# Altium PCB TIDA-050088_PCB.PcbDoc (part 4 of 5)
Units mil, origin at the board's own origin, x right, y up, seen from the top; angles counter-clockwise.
Board outline 8500 x 7000 mil, 8 copper layers (Top Layer, Layer 1 - GND, Signal Layer 2, Layer 3 - GND, Layer 4 - Power, Signal Layer 5, Layer 6 - GND, Bottom Layer), stack 61.6 mil thick; 537 components, 169 nets, 1427 pads, 1411 vias.
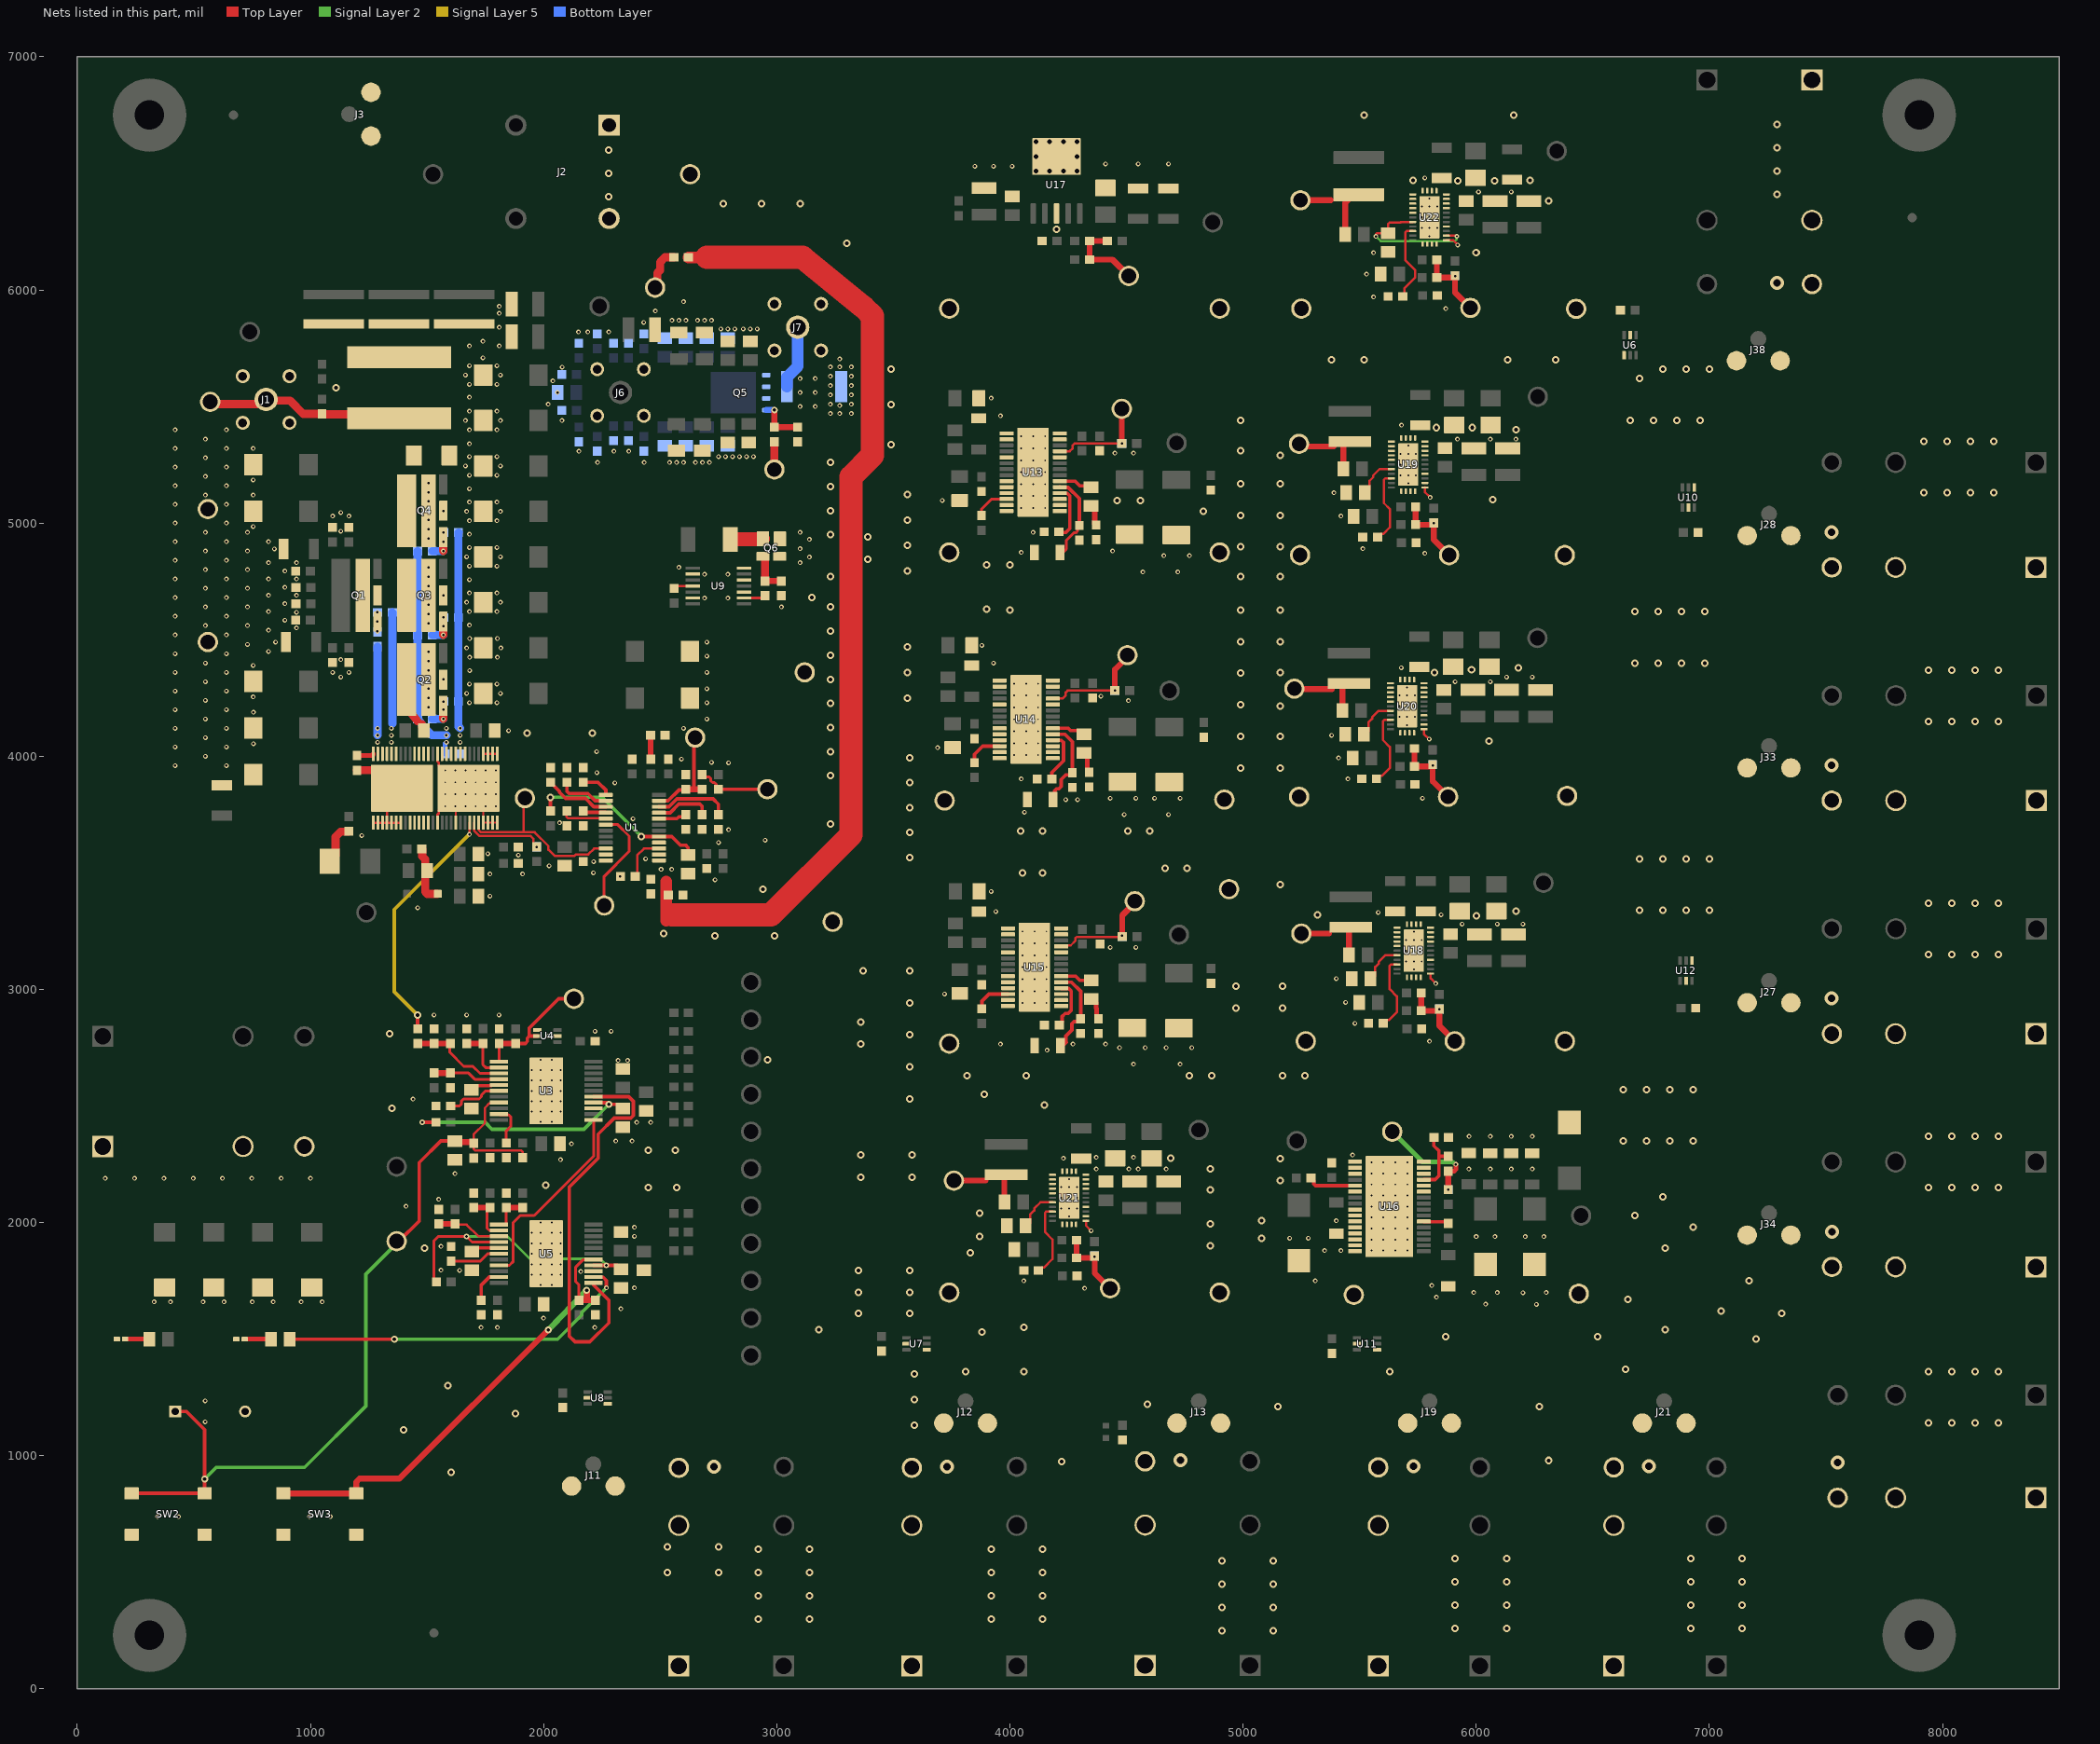
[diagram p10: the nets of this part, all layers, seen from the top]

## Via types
v1: diameter 20, hole 10, Top Layer to Bottom Layer, 671 vias
v2: diameter 32, hole 16, Top Layer to Bottom Layer, tented both sides, 369 vias
v3: diameter 19.68, hole 7.87, Top Layer to Bottom Layer, 176 vias
v4: diameter 19.68, hole 7.87, Top Layer to Bottom Layer, tented both sides, 60 vias
v5: diameter 32, hole 16, Top Layer to Bottom Layer, 30 vias
v6: diameter 56, hole 28, Top Layer to Bottom Layer, 26 vias
v7: diameter 30, hole 15, Top Layer to Bottom Layer, 24 vias
v8: diameter 60, hole 32, Top Layer to Bottom Layer, 22 vias
v9: diameter 20, hole 10, Top Layer to Bottom Layer, tented both sides, 15 vias
v10: diameter 31.5, hole 19.68, Top Layer to Bottom Layer, 10 vias
v11: diameter 24, hole 12, Top Layer to Bottom Layer, 6 vias
v12: diameter 20, hole 8, Top Layer to Bottom Layer, tented both sides, 1 vias
v13: diameter 28, hole 14, Top Layer to Bottom Layer, 1 vias

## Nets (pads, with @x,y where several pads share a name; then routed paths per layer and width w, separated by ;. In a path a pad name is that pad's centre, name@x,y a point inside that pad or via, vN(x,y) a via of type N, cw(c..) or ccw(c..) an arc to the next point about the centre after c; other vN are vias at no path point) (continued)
GND: C1.1 C2.1 C3.1 C4.1 C5.1 C6.2 C7.2 C8.2 C9.2 C10.2 C11.2 C12.2 C13.2 C14.2 C15.2 C16.2 C25.2 C26.2 C27.2 C28.2 C32.1 C33.1 C34.1 C35.1 C36.1 C37.1 C38.1 C39.1 C40.1 C41.1 C43.2 C44.1 C45.1 C46.1 C47.1 C48.2 C49.2 C50.2 C51.2 C52.2 C53.2 C54.2 C55.2 C56.2 C57.2 C58.2 C59.2 C60.2 C61.2 C62.2 C63.2 C64.2 C65.2 C66.2 C67.2 C68.2 C69.2 C70.2 C71.2 C72.2 C73.2 C74.2 C75.2 C76.2 C77.2 C78.2 C79.2 C80.2 C81.2 C82.2 C83.2 C84.2 C85.2 C86.2 C87.2 C88.2 C89.2 C90.1 C91.2 C92.2 C93.2 C94.2 C95.2 C96.2 C97.2 C98.2 C99.1 C100.1 C101.1 C102.1 C103.2 C104.2 C105.2 C106.2 C107.2 C108.2 C109.2 C110.2 C111.2 C113.2 C114.2 C115.2 C117.2 C118.1 C119.1 C120.2 C121.2 C122.2 C123.2 C124.2 C125.2 C126.2 C127.2 C128.2 C129.2 C130.2 C131.2 C132.2 C133.2 C134.2 C135.2 C136.2 C138.2 C139.2 C140.2 C141.2 C142.2 C143.2 C147.2 C148.2 C149.2 C150.2 C151.2 C152.2 C153.2 C154.2 C155.2 C156.2 C157.2 C158.2 C159.2 C160.2 C161.2 C164.2 C165.2 C168.2 C169.2 C170.2 C171.2 C172.2 C173.2 C174.2 C175.2 C176.2 C177.2 C178.2 C179.2 C180.2 C181.2 C182.2 C185.2 C186.2 C188.2 C189.2 C190.2 C191.2 C192.2 C193.2 C194.2 C196.2 D3.2 D4.2 D5.2 J1.2 J1.3 J1.4 J1.5 J2.1 J3.2 J3.3 J5.1 J5.2 J6.2 J6.3 J6.4 J6.5 J7.2 J7.3 J7.4 J7.5 J11.2 J11.3 J12.2 J12.3 J13.2 J13.3 J14.1 J14.2 J15.1 J15.2 J16.1 J16.2 J19.2 J19.3 J21.2 J21.3 J22.1 J22.2 J23.1 J23.2 J24.1 J24.2 J27.2 J27.3 J28.2 J28.3 J29.1 J29.2 J30.1 J30.2 J33.2 J33.3 J34.2 J34.3 J35.1 J35.2 J36.1 J36.2 J38.2 J38.3 J39.1 J39.2 pad.15 pad.19 pad.25 pad.26 pad.27 pad.28 pad.29 pad.30 pad.31 pad.32 pad.42 pad.58 Q2.4 Q2.5 Q3.4 Q3.5 Q4.4 Q4.5 Q6.3 Q6.4 R16.1 R17.1 R24.1 R26.1 R35.1 R37.1 R38.1 R50.1 R51.1 R52.1 R55.1 R56.1 R57.1 R58.1 R60.1 R67.1 R69.1 R70.1 R71.1 R72.1 R73.1 R75.1 R78.1 R89.1 R90.1 R91.1 R92.1 R93.1 R94.1 R95.1 R96.1 R107.1 R108.1 R109.1 R110.1 R114.1 R123.1 R124.1 R125.1 R126.1 R133.1 R134.1 R135.1 R136.1 R140.1 R141.1 SW1.2 SW2.2 SW2.4 SW3.2 SW3.4 TP10.1 TP11.1 TP12.1 TP13.1 TP14.1 TP15.1 TP17.1 TP40.1 TP41.1 TP42.1 TP43.1 TP44.1 TP45.1 TP46.1 TP55.1 TP56.1 TP57.1 TP58.1 TP59.1 TP60.1 TP61.1 TP64.1 TP65.1 TP74.1 TP75.1 TP76.1 TP77.1 TP78.1 TP79.1 TP88.1 TP89.1 TP90.1 TP91.1 TP92.1 TP93.1 TP98.1 TP99.1 TP100.1 U3.14 U3.23 U4.2 U4.4 U5.14 U5.23 U6.2 U6.4 U7.2 U7.4 U8.2 U8.4 U9.3 U9.5 U9.7 U9.9 U9.11 U9.13 U10.2 U10.4 U11.2 U11.4 U12.2 U12.4 U13.1 U13.2 U13.5 U13.9 U13.10 U13.11 U13.13 U13.14 U13.15 U13.16 U13.17 U13.24 U13.27 U13.28 U13.29 U14.1 U14.2 U14.5 U14.9 U14.10 U14.11 U14.13 U14.14 U14.15 U14.16 U14.17 U14.24 U14.27 U14.28 U14.29 U15.1 U15.2 U15.5 U15.9 U15.10 U15.11 U15.13 U15.14 U15.15 U15.16 U15.17 U15.24 U15.27 U15.28 U15.29 U16.1 U16.2 U16.3 U16.6 U16.9 U16.10 U16.11 U16.12 U16.13 U16.14 U16.15 U16.16 U16.27 U16.28 U16.30 U16.31 U16.32 U16.33 U17.3 U17.6 U18.12 U18.13 U18.14 U18.15 U18.19 U18.23 U18.24 U18.25 U18.26 U18.27 U18.28 U18.29 U18.30 U18.31 U19.12 U19.13 U19.14 U19.15 U19.17 U19.19 U19.23 U19.24 U19.25 U19.26 U19.27 U19.28 U19.29 U19.30 U19.31 U20.12 U20.13 U20.14 U20.15 U20.17 U20.19 U20.23 U20.24 U20.25 U20.26 U20.27 U20.28 U20.29 U20.30 U20.31 U21.12 U21.13 U21.14 U21.15 U21.17 U21.19 U21.23 U21.24 U21.25 U21.26 U21.27 U21.28 U21.29 U21.30 U21.31 U22.12 U22.13 U22.14 U22.15 U22.19 U22.23 U22.24 U22.25 U22.26 U22.27 U22.28 U22.29 U22.30 U22.31 | length 1005.2
  Top Layer w8: v4(1621.79,3786.03) 1623.75,3784.06 pad.19@1623.75,3715.16 ; pad.58@1677.89,3862.8 1736.94,3803.75 pad.58@1741.86,3803.75 ; v4(1708.4,3837.21) pad.58@1741.86,3803.75 ; pad.26@1761.55,3715.08 1761.64,3715.16 pad.28@1800.92,3715.16 ; pad.26@1761.55,3715.16 pad.25@1741.86,3715.16 pad.58@1741.86,3803.75 ; U5.14@2209.31,1786.68 U5.14@2213.87,1791.24
  Top Layer w10: pad.15@1545.01,3715.16 1545.12,3715.27 1545.12,3750.12 1549.98,3754.98 1549.98,3767.32 pad.58@1620.83,3838.17 ; pad.42@1545.01,4010.44 1545.01,4009.55 1545.12,4009.45 1545.12,3977.32 1550.67,3971.77 1550.67,3958.11 1573.56,3935.22 1577.92,3939.57 v4(1578.48,3939.57) ; v4(1621.79,3837.21) pad.58@1620.83,3838.17 ; pad.58@1677.89,3862.8 1645.47,3862.8 pad.58@1620.83,3838.17 ; pad.32@1741.86,4010.44 pad.30@1781.23,4010.44 ; pad.30@1781.23,4010.44 1781.32,4010.44 pad.29@1800.92,4010.44 ; C95.2@2559.7,4720 2569.7,4730 U9.11@2637.8,4730
  Top Layer w35: TP10.1@2478.22,6010 2488.17,6019.95 2488.17,6072.57 2500.05,6084.45 2500,6084.5 2500,6119.5 2520.5,6140 R17.1@2558.5,6140
  other v1: 345,738.5 435,738.5 995,738.5 1085,738.5 548.5,1145 548.5,1235 1731.99,1550 1801.99,1550 2220,1550 2000,1590 2331.99,1630 6258.84,1648.88 6040,1650 330,1660 400,1660 540,1660 630,1660 750,1660 840,1660 960,1660 1050,1660 5830,1680 6200.58,1698.72 5990,1700 6090,1700 6300,1700 4320,1717.91 2390,1720 5810,1730 4059.57,1750 5310,1750 2160,1790 1640,1794.75 1560,1795.55 5350,1880 5420,1880 1560,1897.74 5200,1933.39 5280,1933.39 6000,1940 6080,1940 6210,1940 6290,1940 2390,1941.24 2390,1980 5400,2007.91 1410,2070 1550,2100 120,2190 245.71,2190 371.43,2190 497.14,2190 622.86,2190 748.57,2190 874.29,2190 1000,2190 1620,2210 4370,2230 4510,2230 4550,2230 4670,2230 5968.12,2230 6060,2230 6150,2230 6240,2230 2072.73,2270 4230,2275.67 4370,2280 4530,2280 5470,2290 2120,2338.05 2310,2350 2380,2350 5970,2370 6060,2370 6150,2370 6240,2370 2400,2430 2460,2430 1440,2530 4530,2680 4730,2680 2319.29,2695.94 2360.2,2695.94 4160,2740 4470,2750 4580,2750 4670,2750 4780,2750 3960,2765.25 4270,2765.25 4410,2765.25 5800,2777.8 2020,2800 2220.73,2820 2290,2820 5480,2854.7 1530,2890 1670,2890 1809.16,2890 5440,2943.93 3720,2980 5400,3045.9 4430,3180 4540,3180 5940,3280 6090,3280 6200,3280.4 5850,3320 5580,3330 3940,3334.06 1460,3350 1770,3400 3920,3420 1770,3495 1910,3495 1891.5,3575.59 1760.75,3581.54 2950,3640 1220,3660 4490,3750 4680,3750 4063.04,3760 4240,3814.21 4290,3814.21 4430,3820 4540,3820 4620,3820 4730,3820 5770,3820 4048.75,3902.59 5450,3903.15 420,3960 640,3960 5410,3992.38 550,4000 3690,4037.15 420,4040 640,4040 755,4053.7 550,4080 5380,4090 1850,4110 420,4120 640,4120 2600,4120 550,4160 2700,4160 755,4188.7 420,4200 640,4200 1506.99,4210 1682.38,4230 1800.37,4230 2700,4230 4508,4238.97 550,4240 1506.99,4249.68 754.77,4255 4390,4258.11 1670,4270 1815.37,4270 420,4280 640,4280 1506.99,4289.37 2700,4290 1682.38,4310 1800.37,4310 550,4320 5910,4320 6060,4320 1506.99,4329.05 1570,4330 1130,4340 6130,4340 6240,4340 420,4360 640,4360 1095,4360 1165.02,4360 2700,4360 1683.43,4367.5 1506.99,4368.74 5678.9,4380 754.77,4390 550,4400 3930,4400 1506.99,4408.42 1130,4415 1683.43,4425 1801.42,4425 2700,4430 420,4440 640,4440 1506.99,4448.11 820,4450 1670,4465 1816.42,4465 3880,4475.74 730,4480 850,4490 2700,4490 1683.43,4505 1801.42,4505 420,4520 640,4520 820,4540 940,4550 550,4560 730,4560 1682.01,4562.5 1506.99,4570.95 890,4583.94 420,4600 640,4600 1506.99,4610.63 940,4617.01 820,4620 1682.01,4620 1800,4620 550,4640 730,4640 3020,4640 1506.99,4650.32 890,4653.94 1670,4660 1815,4660 2690,4678.82 2790,4678.82 420,4680 640,4680 820,4690 940,4690 1506.99,4690 1570,4690 1682.01,4700 1800,4700 550,4720 730,4720 890,4723.94 1506.99,4729.68 1682.01,4757.5 420,4760 640,4760 820,4760 940,4760 1506.99,4769.37 2690,4780 2790,4780 4570,4790 4720,4790 890,4793.94 550,4800 730,4800 1506.99,4809.05 2580.25,4810 1682.01,4815 1800,4815 820,4830 940,4830 3100,4830 420,4840 640,4840 3140,4854.21 1670,4855 1815,4855 4660,4860 4770,4860 5780,4870 4048.75,4874.21 550,4880 730,4880 4440,4880 845,4888.94 3100,4890 5513.71,4890 1682.01,4895 1800,4895 420,4920 640,4920 820,4920 3140,4930 1506.99,4933.94 1682.01,4952.5 550,4960 730,4960 3100,4960 4099.93,4960 1130,4965 1506.99,4973.62 754.77,4985 420,5000 640,5000 1682.01,5010 1800,5010 1506.99,5013.31 1095.02,5030 1165.02,5030 5420,5030 1130,5045 1670,5050 1815,5050 1570,5051.3 1506.99,5052.99 420,5080 640,5080 1682.01,5090 1800,5090 1506.99,5092.68 3710,5097.15 550,5120 754.77,5120 5390,5130 1506.99,5132.36 1682.01,5147.5 420,5160 640,5160 1506.99,5172.05 754.77,5185 550,5200 1682.01,5205 1800,5205 420,5240 640,5240 1665,5245 1815,5245 2231.36,5260 2431.3,5260 2540,5260 2570,5260 2600,5260 2651.14,5260 2681.14,5260 2711.14,5260 550,5280 1682.01,5285 1800,5285 2750,5285 2780,5285 2810,5285 2840,5285 2870,5285 2900,5285 4450,5300 4530,5300 2151.36,5308.5 2301.3,5308.5 2365.35,5308.5 420,5320 640,5320 754.77,5320 1682.01,5340 550,5360 5920,5360 6060,5360 6170,5360 420,5400 640,5400 1682.01,5400 1800,5400 5680,5419.68 1665,5440 1815,5440 2078.5,5440 3960,5460 3230,5470 3270,5470 3320,5470 1682.01,5480 1800,5480 3100,5500 3165,5500 3270,5503.7 2020,5510 3230,5510 3320,5510 3920,5535.74 1682.01,5540 3230,5550 3320,5550 2060,5560 3100,5560 3165,5560 3230,5590 3320,5590 1682.01,5595 1800,5595 2040,5610 3100,5620 3165,5620 3230,5630 3320,5630 1665,5635 1815,5635 2080.14,5668.37 3230,5670 3270,5670 3320,5670 1682.01,5675 1800,5675 3270,5703.7 1740,5708.5 1682.01,5760 1810,5760 1740,5780 2150,5820.24 2190,5820.24 2280,5820.24 2760,5832.89 2790,5832.89 2820,5832.89 2856.73,5832.89 2886.73,5832.89 2916.73,5832.89 1810,5840 2430,5860.24 2550,5870 2580,5870 2610,5870 2660,5869.97 2690,5869.97 2720,5869.97 1810,5900 2479.59,5910 5870,5920 1810,5930 2600,5950 5560,5970 5530,6067.7 5560,6160 6010,6420 6150,6420 5780,6479.9 3850,6530 3930,6530 4010,6530 4410,6540 4550,6540 4680,6540
  other v2: 4910,250 5130,250 5910,260 6130,260 6920,260 7140,260 2920,300 3140,300 3920,300 4140,300 4910,350 5130,350 5910,360 6130,360 6920,360 7140,360 2920,400 3140,400 3920,400 4140,400 4910,450 5130,450 5910,460 6130,460 6920,460 7140,460 2530,500 2750,500 2920,500 3140,500 3920,500 4140,500 4910,550 5130,550 5910,560 6130,560 6920,560 7140,560 2920,600 3140,600 3920,600 4140,600 2530,610 2750,610 1603.49,930 4222.39,975.96 6310,980 1400,1110 3590,1130 7940,1140 8040,1140 8140,1140 8240,1140 1880,1180 5150,1210 6270,1210 4590,1220 3590,1240 1590,1300 3590,1350 3810,1360 4060,1360 5630,1360 7940,1360 8040,1360 8140,1360 8240,1360 6640,1370 7200,1500 5870,1510 6520,1510 3879.4,1530 3180,1540 6810,1540 4060,1550 3350,1610 3570,1610 7310,1610 7050,1620 6650,1670 3350,1700 3570,1700 7170,1750 3350,1794.75 3570,1794.81 3830,1870 1490,1890 6810,1890 4860,1900 5080,1933.39 3870,1940 6930,1980 4860,1994.81 5080,2007.91 6680,2030 3870,2040 6800,2110 4860,2140 2450,2150 2570,2150 7940,2150 8040,2150 8140,2150 8240,2150 2010,2160 5160,2180 3360,2195.19 3580,2195.19 4860,2230 5160,2274.89 4690,2275.67 3360,2289.94 3580,2290 2450,2310 2565,2310 6630,2350 6730,2350 6830,2350 6930,2350 7940,2370 8040,2370 8140,2370 8240,2370 1350,2490 4147.44,2503.23 3570,2530 3890,2550 6630,2570 6730,2570 6830,2570 6930,2570 3817.03,2630 4070,2630 4770,2630 4864.81,2630 5170,2630 5264.81,2630 3570,2667.5 2960,2698.66 3360,2765.25 3570,2805 1340,2810 3360,2860 4970,2920 5170,2920 3570,2942.5 4970,3014.81 5170,3014.81 3370,3080 3570,3080 7940,3150 8040,3150 8140,3150 8240,3150 2735.23,3230 2990,3230 2515,3240 6001.07,3315.71 5320,3320 6170,3335.56 6700,3340 6800,3340 6900,3340 7000,3340 7940,3370 8040,3370 8140,3370 8240,3370 2940,3430 5160,3450 4054.65,3500 4140,3500 4665.19,3520 4760,3520 6700,3560 6800,3560 6900,3560 7000,3560 3570,3566.47 3570,3673.25 4045.19,3680 4140,3680 4505.19,3680 4600,3680 3230,3710 3570,3780.02 3570,3886.79 3230,3916.67 4990,3950 5160,3950 3570,3993.57 3230,4020 6055.41,4065.44 4990,4085.45 5160,4085.45 1930,4100 2210,4100 3230,4123.33 7940,4150 8040,4150 8140,4150 8240,4150 5160,4214.68 4990,4220.91 3230,4226.67 3560,4250 3230,4330 4990,4356.36 3560,4359.05 5160,4360 5821.02,4360 7940,4370 8040,4370 8140,4370 8240,4370 5980.02,4370.59 6180,4380 6680,4400 6780,4400 6880,4400 6980,4400 3230,4433.33 3560,4468.1 4990,4491.82 5160,4491.82 3230,4536.67 6680,4620 6780,4620 6880,4620 6980,4620 3999.63,4626.75 4990,4627.27 5160,4627.27 3900,4630 3230,4640 3150,4680 3230,4770 4990,4770 5160,4770 3560,4795.25 3900,4820 4000,4820 3390,4845.19 4990,4898.18 5160,4898.18 3560,4904.3 3390,4940 3230,4950 3560,5013.35 4990,5033.64 5160,5033.64 4830,5050 3230,5053.33 4460,5097.15 4560,5097.15 6070,5100 3560,5122.4 7920,5130 8020,5130 8120,5130 8220,5130 3230,5156.67 4990,5169.09 5160,5169.09 3230,5260 5160,5290 4990,5310 3490,5336.5 7920,5350 8020,5350 8120,5350 8220,5350 6170,5400 5829.19,5409.49 5982.05,5409.49 4990,5440 6660,5440 6760,5440 6860,5440 6960,5440 3490,5508.15 1110,5580 6701.07,5620 3490,5660 6800,5660 6900,5660 7000,5660 5380,5700 5520,5700 6135.71,5700 6340,5700 6000,6160 3300,6200 2770,6370 2935,6370 3100,6370 6310,6381.21 2280,6400 7290,6410 5921.58,6467.45 6078.3,6467.45 5730,6470 6230,6470 2280,6500 7290,6510 2280,6600 7290,6610 7290,6710 5520,6750 6160,6750
  other v3: 1987.5,1732.58 2035.13,1732.58 1949.9,1776.48 1987.5,1776.48 2035.13,1776.48 2072.73,1776.48 1949.9,1821.36 1987.5,1821.36 2035.13,1821.36 2072.73,1821.36 1949.9,1866.24 1987.5,1866.24 2035.13,1866.24 2072.73,1866.24 1949.9,1911.13 1987.5,1911.13 2035.13,1911.13 2072.73,1911.13 1949.9,1956.01 1987.5,1956.01 2035.13,1956.01 2072.73,1956.01 1987.5,1999.91 2035.13,1999.91 4254.29,2025.63 4220.83,2060.67 4254.29,2060.67 4287.75,2060.67 4220.83,2106.34 4254.29,2106.34 4287.75,2106.34 4220.83,2152.01 4254.29,2152.01 4287.75,2152.01 4254.29,2187.05 1987.62,2431.34 2035.26,2431.34 1950.02,2475.24 1987.62,2475.24 2035.26,2475.24 2072.85,2475.24 1950.02,2520.12 1987.62,2520.12 2035.26,2520.12 2072.85,2520.12 1950.02,2565 1987.62,2565 2035.26,2565 2072.85,2565 1950.02,2609.88 1987.62,2609.88 2035.26,2609.88 2072.85,2609.88 1950.02,2654.76 1987.62,2654.76 2035.26,2654.76 2072.85,2654.76 1987.62,2698.66 2035.26,2698.66 4054.65,2941.61 4105.83,2941.61 4157.01,2941.61 4054.65,2992.8 4105.83,2992.8 4157.01,2992.8 4054.65,3043.98 4105.83,3043.98 4157.01,3043.98 5732.72,3085.52 4054.65,3095.16 4105.83,3095.16 4157.01,3095.16 5699.26,3120.56 5732.72,3120.56 5766.19,3120.56 4054.65,3146.34 4105.83,3146.34 4157.01,3146.34 5699.26,3166.23 5732.72,3166.23 5766.19,3166.23 4054.65,3197.52 4105.83,3197.52 4157.01,3197.52 5699.26,3211.9 5732.72,3211.9 5766.19,3211.9 5732.72,3246.94 4054.65,3248.7 4105.83,3248.7 4157.01,3248.7 4018.75,4004.66 4069.93,4004.66 4121.11,4004.66 4018.75,4055.85 4069.93,4055.85 4121.11,4055.85 4018.75,4107.03 4069.93,4107.03 4121.11,4107.03 5704.08,4133.97 4018.75,4158.21 4069.93,4158.21 4121.11,4158.21 5670.62,4169.01 5704.08,4169.01 5737.55,4169.01 4018.75,4209.39 4069.93,4209.39 4121.11,4209.39 5670.62,4214.68 5704.08,4214.68 5737.55,4214.68 5670.62,4260.35 5704.08,4260.35 5737.55,4260.35 4018.75,4260.57 4069.93,4260.57 4121.11,4260.57 5704.08,4295.39 4018.75,4311.75 4069.93,4311.75 4121.11,4311.75 4048.75,5064.66 4099.93,5064.66 4151.11,5064.66 4048.75,5115.85 4099.93,5115.85 4151.11,5115.85 4048.75,5167.03 4099.93,5167.03 4151.11,5167.03 5708.43,5170.42 5674.97,5205.46 5708.43,5205.46 5741.9,5205.46 4048.75,5218.21 4099.93,5218.21 4151.11,5218.21 5674.97,5251.13 5708.43,5251.13 5741.9,5251.13 4048.75,5269.39 4099.93,5269.39 4151.11,5269.39 5674.97,5296.8 5708.43,5296.8 5741.9,5296.8 4048.75,5320.57 4099.93,5320.57 4151.11,5320.57 5708.43,5331.84 4048.75,5371.75 4099.93,5371.75 4151.11,5371.75 5799.85,6230.64 5766.38,6265.68 5799.85,6265.68 5833.31,6265.68 5766.38,6311.35 5799.85,6311.35 5833.31,6311.35 5766.38,6357.01 5799.85,6357.01 5833.31,6357.01 5799.85,6392.05
  other v4: 5550.78,1879.83 5601.96,1879.83 5653.14,1879.83 5704.32,1879.83 5550.78,1927.08 5601.96,1927.08 5653.14,1927.08 5704.32,1927.08 5550.78,1974.32 5601.96,1974.32 5653.14,1974.32 5704.32,1974.32 5550.78,2021.57 5601.96,2021.57 5653.14,2021.57 5704.32,2021.57 5550.78,2068.81 5601.96,2068.81 5653.14,2068.81 5704.32,2068.81 5550.78,2116.05 5601.96,2116.05 5653.14,2116.05 5704.32,2116.05 5550.78,2163.3 5601.96,2163.3 5653.14,2163.3 5704.32,2163.3 5550.78,2210.54 5601.96,2210.54 5653.14,2210.54 5704.32,2210.54 5550.78,2257.79 5601.96,2257.79 5653.14,2257.79 5704.32,2257.79 1578.48,3786.03 1665.09,3786.03 1708.4,3786.03 1751.71,3786.03 1795.01,3786.03 1578.48,3837.21 1665.09,3837.21 1751.71,3837.21 1795.01,3837.21 1578.48,3888.39 1621.79,3888.39 1665.09,3888.39 1708.4,3888.39 1751.71,3888.39 1795.01,3888.39 1621.79,3939.57 1665.09,3939.57 1708.4,3939.57 1751.71,3939.57 1795.01,3939.57
  other v5: 4200,6260
  other v8: 2731.3,952.82 3730.78,952.82 5731.3,954.53 6741.3,954.53 7550,971.3 4731.3,980.53 7525.63,1961.3 7524.83,2961.3 7524.83,3961.3 7525.09,4961.3 7290,6029.53
  other v10: 4111.42,6509.06 4170.47,6509.06 4229.53,6509.06 4288.58,6509.06 4111.42,6572.05 4288.58,6572.05 4111.42,6635.04 4170.47,6635.04 4229.53,6635.04 4288.58,6635.04
GND_0V8: C17.2 C18.2 C19.2 C20.2 C21.2 C22.2 C23.2 C24.2 C25.1 R3.2 R4.1 R8.1 R9.1 R10.1 R11.1 R12.1 R13.1 R14.1 R16.2 R17.2 U1.11 U1.12 U1.13 U1.14 U1.16 | length 4203.2
  Top Layer w15: U1.16@2495,3629.76 U1.16@2496.36,3628.41
  Top Layer w50: 2525.82,3295.34 2526.35,3405.04 2526.63,3462.5 ; R17.2@2621.5,6140 2680,6140
  Top Layer w100: 2550,3320 2974.88,3319.68 3318,3662.8 3318,5197.91 3410,5289.91 3410,5888.46 3373.22,5925.25 3110,6140 2700,6140
  other v1: 2735.23,3470 2329,3485 2214,3500 2504,3515 2549,3515 2024,3530 2215.08,3548.5 2437.65,3560.46 2750,3630 2793.7,3685 2068.28,3715.08 2384,3732.13 2305.12,3885.61 2228.83,3930 2793.7,3971.34 2720,3973.89 2591.54,3987.38 2227.78,4020
HICC_0V8: R8.2 U1.5 | length 196.9
  Top Layer w10: R8.2@2100,3765.1 2098.86,3763.96 2098.86,3739.46 2104.72,3733.6 2265.18,3733.6 U1.5@2266.65,3732.13
HOH_0V8: pad.51 pad.52 pad.53 R20.1 | length 476.2
  Bottom Layer w35: R20.1@1351.13,4617.01 1351.13,4616.17 1351.5,4615.81 1351.5,4140.93
  other v1: 1346.87,4060 1346.87,4090 1346.87,4120
HOL_0V8: pad.54 pad.55 pad.56 R21.1 R22.2 | length 453.6
  Top Layer w20: R22.2@1200,4002.99 1265.33,4002.99 1269.42,4007.09 pad.56@1269.42,4010.44
  Bottom Layer w35: v1@1287.45,4120.37 R21.1@1287.45,4469.53 ; v1(1287.82,4090) v1(1287.82,4120)
  other v1: 1287.82,4060
HYS_SEQ1: R56.2 U3.6 | length 245.8
  Top Layer w12: R56.2@1601.5,2500 1639.18,2500 1646.5,2507.32 1646.5,2519.97 1656.53,2530 1723.47,2530 1733.5,2540.03 1733.5,2546.99 1751.51,2565 U3.6@1808.88,2565
HYS_SEQ2: R71.2 U5.6 | length 218.3
  Top Layer w12: R71.2@1603.49,1834.75 1728.5,1834.75 1760,1866.24 U5.6@1808.76,1866.24
LEB_0V8: R9.2 U1.4 | length 99.7
  Top Layer w15: R9.2@2170,3765.1 2176.02,3759.08 2265.3,3759.08 U1.4@2266.65,3757.72
LOH_0V8: pad.36 pad.37 pad.38 R28.1 R29.1 R30.1 | length 844.5
  Bottom Layer w20: R30.1@1636.66,4960 R30.1@1636.94,4959.71
  Bottom Layer w35: R30.1@1636.66,4960 1635.97,4960 1634.77,4958.8 R29.1@1634.77,4595 R28.1@1634.77,4235 1634.77,4127.54 v1(1642.15,4120.16)
  other v1: 1642.15,4060.16 1642.15,4090.16
LOL_0V8: pad.39 pad.40 pad.41 R32.1 R33.1 R34.1 R35.2 | length 924.1
  Bottom Layer w20: R35.2@1578.5,4010 1578.5,4055.57 v1(1583.09,4060.16)
  Bottom Layer w35: R32.1@1459.57,4160 1460.55,4160 1475,4140 1479.38,4131.57 1520.78,4090.16 v1(1583.09,4090.16) ; R33.1@1459.57,4520 R33.1@1460,4520 ; R32.1@1460,4163.5 R33.1@1460,4520 ; R34.1@1460,4879.12 R33.1@1460,4520
  other v1: 1583.09,4120.16
NetC22_1: C22.1 R7.1 | length 103.2
  Top Layer w25: C22.1@2458.5,4090 2458.5,4084.55 2459.25,4083.8 2459.25,3994.57 2460,3993.82 R7.1@2460,3987.38
NetC24_1: C24.1 U1.22 | length 325.3
  Top Layer w15: U1.22@2496.36,3784.67 U1.22@2495,3783.31 2538.01,3783.31 2571.93,3817.23 2727.23,3817.23 2750,3794.46 C24.1@2750,3749.59
NetC112_2: C112.2 R95.2 | length 94.6
  Top Layer w12: R95.2@4370,4991.5 R95.2@4370,4992.48
  Top Layer w25: C112.2@4347.96,5074.04 4351.3,5074.04 4363.8,5061.54 4363.8,4997.7 R95.2@4370,4991.5
NetC116_2: C116.2 R96.2 | length 92.7
  Top Layer w12: R96.2@4340,3931.5 R96.2@4340,3932.48
  Top Layer w20: C116.2@4317.96,4014.04 4331.3,4000.7 4331.3,3940.2 R96.2@4340,3931.5
NetC120_1: C120.1 R97.1 U16.29 | length 285.8
  Top Layer w15: U16.29@5775.19,2183.97 5823.97,2183.97 5840,2200 5840,2285 ; C120.1@5818.5,2365 5818.5,2329.64 5840,2308.14 5840,2285 ; R97.1@5880,2283.87 5841.13,2283.87 5840,2285
NetC137_2: C137.2 R110.2 | length 102
  Top Layer w12: R110.2@4380,2874.22 R110.2@4380,2875.2
  Top Layer w20: C137.2@4349.39,2958.79 4355,2958.79 4370,2943.79 4370.89,2943.79 4370.89,2919.11 4371.3,2918.7 4371.3,2882.92 R110.2@4380,2874.22
NetC144_1: C144.1 R112.1 R113.2 TP63.1 | length 354.5
  Top Layer w25: R112.1@4418.5,6210 R113.2@4341.5,6210 C144.1@4341.5,6130 4440,6130 TP63.1@4510,6060
NetC162_1: C162.1 R117.1 R118.1 R121.2 TP72.1 | length 323.2
  Top Layer w25: R121.2@5764.22,2984.58 5764.25,2984.54 C162.1@5764.29,2908.21 C162.1@5764.29,2908.21 5835.43,2908.21 5842.01,2914.8 v9(5842.01,2915.78) 5842.01,2843.86 TP72.1@5908.08,2777.8
NetC163_1: C163.1 R119.1 R120.1 R122.2 TP73.1 | length 374.4
  Top Layer w10: 5765.55,5000.69 R119.1@5817.73,5000.69
  Top Layer w25: R122.2@5739.93,5069.48 5739.97,5069.45 C163.1@5740,4993.11 C163.1@5740,4993.11 5811.14,4993.11 v9(5817.73,4999.7) ; R119.1@5817.73,5000.69 v9(5817.73,4999.7) ; TP73.1@5883.79,4862.7 5817.73,4928.76 v9(5817.73,4999.7)
NetC183_1: C183.1 R127.1 R128.1 R131.2 TP86.1 | length 322.2
  Top Layer w25: R131.2@5735.58,4033.03 R131.2@5735.58,4033.03 5735.62,3956.7 C183.1@5735.65,3956.66 5806.79,3956.66 R127.1@5813.38,3963.25 ; R127.1@5813.38,3964.23 R127.1@5813.38,3963.25 ; TP86.1@5879.44,3826.25 5813.38,3892.31 R127.1@5813.38,3963.25
  other v9: 5813.38,3961.28
NetC184_1: C184.1 R129.1 R130.1 R132.2 TP87.1 | length 341.1
  Top Layer w10: R132.2@4271.56,1910.99 4285.26,1924.69 R132.2@4285.79,1924.69
  Top Layer w25: R132.2@4285.79,1924.69 R132.2@4285.79,1924.69 4285.82,1848.36 C184.1@4285.86,1848.32 4356.99,1848.32 4363.58,1854.91 4363.58,1783.97 TP87.1@4429.65,1717.91
  other v9: 4363.58,1852.94
NetC195_1: C195.1 R137.1 R138.1 R139.2 TP97.1 | length 374.4
  Top Layer w10: 5856.96,6060.9 R137.1@5909.14,6060.9
  Top Layer w25: R139.2@5831.35,6129.7 5831.38,6129.66 C195.1@5831.38,6053.37 ; R137.1@5909.14,6060.9 v9(5909.14,6059.92) ; TP97.1@5975.21,5922.91 5909.14,5988.98 v9(5909.14,6059.92) ; C195.1@5831.38,6053.37 C195.1@5831.42,6053.33 ; C195.1@5831.42,6053.33 5902.55,6053.33 v9(5909.14,6059.92)
NetD1_2: D1.2 R15.2 | length 182.3
  Top Layer w35: D1.2@1082.99,3550 1107.99,3575 1107.99,3654.41 1130,3676.42 1163.82,3676.42 1165.02,3677.62 R15.2@1165.02,3678.5
NetD4_1: D4.1 R115.1 | length 104.6
  Top Layer w20: D4.1@205.43,1500 R115.1@310,1500
NetD5_1: D5.1 R116.1 | length 112.3
  Top Layer w20: D5.1@717.72,1500 R116.1@830,1500
NetJ7_1: J7.1 Q5.1 Q5.2 Q5.3 R38.2 | length 274.1
  Bottom Layer w50: R38.2@3043.86,5585 3043.86,5626.34 3090,5672.48 J7.1@3090,5840
NetL1_2: L1.2 R23.1 R25.1 R27.1
NetQ1_1: Q1.1 R20.2 R21.2
  other v1: 1287.5,4535 1287.5,4577.01 1287.14,4617.01
NetQ2_1: Q2.1 R28.2 R32.2 | length 87.2
  Top Layer w10: Q2.1@1570.93,4199.32 Q2.1@1571.21,4199.03
  Top Layer w35: v1(1570,4160) v1(1570,4199.32)
  Bottom Layer w35: R32.2@1522.56,4160 v1(1570,4160)
  other v1: 1570,4235
NetQ3_1: Q3.1 R29.2 R33.2 | length 86.1
  Top Layer w35: v1(1570,4520) v1(1570,4558.64)
  Bottom Layer w35: R33.2@1522.56,4520 v1(1570,4520)
  other v1: 1570,4595
NetQ4_1: Q4.1 R30.2 R34.2 | length 90.2
  Top Layer w10: Q4.1@1571.5,4918.75 Q4.1@1572.74,4920
  Top Layer w35: v1@1570,4879.68 v1(1570,4880) v1(1570,4920) Q4.1@1570.49,4919.51
  Bottom Layer w35: R34.2@1522.56,4880 v1(1570,4880)
  other v1: 1570,4960
NetQ5_4: Q5.4 R36.2 R37.2 | length 208.5
  Top Layer w25: v13(2990,5485) R36.2@2990,5411.5 R37.2@3090,5411.5
  Bottom Layer w25: Q5.4@2955.04,5485 v13(2990,5485)
NetQ6_1: Q6.1 R77.2 R78.2 | length 183
  Top Layer w25: R77.2@2950,4751.5 R78.2@3020,4751.5
  Top Layer w35: Q6.1@2941.66,4857.03 2948.5,4857.03 2950,4855.53 R77.2@2950,4751.5
NetQ6_2: Q6.2 R76.1 | length 141.2
  Top Layer w50: R76.1@2800.55,4930 R76.1@2801.3,4930.75
  Top Layer w60: R76.1@2801.3,4930.75 2802.05,4931.5 2939.64,4931.5 Q6.2@2940.66,4932.52
NetR1_1: R1.1 R2.2 TP2.1 | length 318.7
  Top Layer w12: R2.2@2680,3921.54 2689.86,3911.67 2710,3911.67 2717.32,3904.35 2717.32,3894.35 2724.64,3887.03 2732.97,3887.03 2740,3880 2740,3868.54 R1.1@2750,3858.54
  Top Layer w15: R1.1@2750,3858.54 TP2.1@2960,3858.54
NetR3_1: R3.1 U1.15 | length 199.3
  Top Layer w10: R3.1@2392.99,3485 2401.35,3493.36 2401.35,3575.2 2430.33,3604.17 U1.15@2495,3604.17
NetR18_1: pad.23 R18.1 R19.2 | length 343.3
  Top Layer w10: pad.23@1702.49,3715.16 1702.49,3714.28 1702.6,3714.17 1702.72,3714.06 1702.72,3680.04 1725.23,3657.53 1835.1,3657.53 1835.14,3657.57 1945,3657.57 1956.3,3646.27 1956.3,3625.2 v1(1970,3611.5)
NetR36_1: R36.1 TP18.1 | length 132.6
  Top Layer w35: R36.1@2990,5348.5 TP18.1@2990,5230 TP18.1@2999.95,5239.95
NetR44_1: R44.1 R50.2 TP27.1 U3.1 U4.5 | length 541.8
  Top Layer w12: U3.1@1808.88,2690 1809.16,2690 R50.2@1809.16,2768.08
  Top Layer w15: R44.1@1880,2768.08 1921.21,2768.08 1930,2776.86 1930,2791.21 1938.79,2800 ; U4.5@1973.13,2800 1938.79,2800 ; TP27.1@2130,2960 2064,2959.99 1938.79,2834.77 1938.79,2800
  Top Layer w25: R50.2@1809.16,2768.08 R44.1@1880,2768.08
NetR46_1: R46.1 R51.2 U3.2 | length 235
  Top Layer w12: R46.1@1739.79,2768.29 1739.79,2677.47 1752.26,2665 U3.2@1808.88,2665
  Top Layer w25: R51.2@1670,2768.08 1670.21,2768.29 R46.1@1739.79,2768.29
NetR48_1: R48.1 R52.2 R54.2 U3.3 | length 427.2
  Top Layer w12: R48.1@1600,2768.08 1598.05,2766.13 1598.05,2730 1657.58,2670.47 1696.52,2670.47 1727,2640 U3.3@1808.88,2640
  Top Layer w25: R54.2@1460,2768.5 1460.43,2768.08 R52.2@1530,2768.08 ; R52.2@1530,2768.08 R48.1@1600,2768.08
NetR49_1: R49.1 R55.2 U3.4 | length 289.9
  Top Layer w12: R55.2@1600,2641.5 1678.41,2641.5 1704.9,2615 U3.4@1808.88,2615
  Top Layer w25: R49.1@1530,2641.5 R55.2@1600,2641.5
NetR62_1: R62.1 R67.2 U5.1 | length 172.6
  Top Layer w12: U5.1@1808.76,1991.24 1837.44,1991.24 1840,1993.81 R67.2@1840,2064.06
  Top Layer w25: R67.2@1840,2064.06 R62.1@1910,2064.06
NetR64_1: R64.1 R69.2 U5.2 | length 218.8
  Top Layer w12: R64.1@1770,2064.05 1757.39,2051.44 1757.39,1975.89 1767.03,1966.24 U5.2@1808.76,1966.24
  Top Layer w25: R69.2@1700,2064.05 R64.1@1770,2064.05
NetR66_1: R66.1 R70.2 U5.3 | length 280.6
  Top Layer w10: R66.1@1620,1994.06 1622.81,1991.24 1670,1991.24 1719.5,1941.74 1808.26,1941.74 U5.3@1808.76,1941.24
  Top Layer w25: R70.2@1550,1994.05 R66.1@1620,1994.06
NetR77_1: R77.1 U9.2 | length 91.8
  Top Layer w12: U9.2@2862.21,4678.82 2940.32,4678.82 R77.1@2950,4688.5
NetR97_2: R97.2 R98.2 R99.2 TP47.1 | length 466.8
  Top Layer w20: R97.2@5880,2220.88 5880.88,2220 5905,2220 5912.5,2227.5 v1(5912.4,2249.33)
  Top Layer w25: v1(5880,2141.5) R97.2@5880,2220.88
  Signal Layer 2 w20: TP47.1@5640,2390 5770,2260 5897.5,2260 v1(5912.4,2249.33)
NetR103_2: R103.2 U16.5 | length 210.6
  Top Layer w15: R103.2@5291.5,2191.77 5292.48,2191.77 5303.68,2180.57 5303.68,2166.32 5311.62,2158.38 U16.5@5479.91,2158.38
NetR106_1: R106.1 U16.22 | length 108.3
  Top Layer w15: U16.22@5775.19,2004.83 5776.55,2003.47 5872.9,2003.47 R106.1@5880,1996.38
NetU3_12: U3.12 U5.8 | length 852.9
  Top Layer w12: U5.8@1808.76,1816.24 1852.97,1816.24 1870,1833.27 1870,2000 1900,2030 1960,2030 2214.28,2284.28 2214.28,2437.44 2214,2437.72 U3.12@2214,2440
NetU3_16: U3.16 U5.12 | length 1759.2
  Top Layer w10: U5.12@2242.71,1741.24 U5.12@2246.28,1737.68
  Top Layer w15: U5.12@2213.87,1741.24 2214,1741.12 2214,1732.52 2280,1666.52 2280,1570 2198.5,1488.5 2134.8,1488.5 2110.49,1512.81 2110.49,2152.92 2233.78,2276.2 2233.78,2379.37 2302.91,2448.5 2374.09,2448.5 2385,2459.41 2385,2520.59 2365.59,2540 U3.16@2214,2540
OUTA_0V8: pad.24 TP1.1 U1.10 | length 793.5
  Top Layer w10: pad.24@1722.18,3715.16 1722.18,3714.28 1722.4,3714.06 1722.4,3682.99 1731.86,3673.53 1823.41,3673.53 1823.45,3673.57 1915,3673.57 ; TP1.1@1920,3820 1915,3815 1915,3673.57 ; U1.10@2266.65,3604.17 2216.58,3604.17 2191.64,3579.23 2138.64,3579.23 2131.08,3571.67 2048.68,3571.67 2020.97,3599.39 2020.97,3614.47 1961.87,3673.57 1915,3673.57
OUTS_0V92: R100.1 R101.1 TP52.1 U15.25 | length 459.6
  Top Layer w10: U15.25@4220,3184.72 4223.86,3188.58 4260.9,3188.58 4280.61,3208.3 4280.61,3219.03 4287.06,3225.48 4480.93,3225.48 R101.1@4481.74,3226.29
  Top Layer w25: R101.1@4481.74,3226.29 4481.74,3317.66 4535.59,3371.51 TP52.1@4535.59,3378.36
  other v1: 4481.74,3231.7
OUTS_1V5: R81.1 R82.1 TP39.1 U14.25 | length 462.1
  Top Layer w10: U14.25@4184.11,4247.77 4226.43,4247.77 4239.19,4260.54 4239.19,4273.37 4247.36,4281.54 v1(4450.31,4281.54)
  Top Layer w25: v1(4450.31,4281.54) 4450.31,4372.91 4504.17,4426.76 TP39.1@4504.17,4433.6
OUTS_1V5_GTY: R79.1 R80.1 TP38.1 U13.25 | length 436.3
  Top Layer w10: U13.25@4214.11,5307.77 4256.43,5307.77 4269.19,5320.54 4269.19,5333.37 4277.36,5341.54 v1(4480.31,5341.54)
  Top Layer w25: TP38.1@4480,5490 4480.16,5489.84 4480.16,5341.69 v1(4480.31,5341.54)
PG_0V92: R102.1 U15.12 | length 157.3
  Top Layer w15: R102.1@3879.4,2917.07 3880,2917.67 3880,2950 3910,2980 U15.12@3991.65,2980
PG_1V2: U18.16 | length 52.2
  Top Layer w10: U18.16@5804.57,3067.8 5804.57,3047.35 v9(5826.99,3024.94)
PG_1V2_MEM: U20.16 | length 52.2
  Top Layer w10: U20.16@5775.94,4116.25 5775.94,4095.8 v9(5798.35,4073.39)
PG_1V2_VCCO: U19.16 | length 52.2
  Top Layer w10: U19.16@5780.28,5152.7 5780.28,5132.26 v9(5802.7,5109.84)
PG_1V5: R84.1 U14.12 | length 158
  Top Layer w15: R84.1@3847.98,3972.32 3847.98,4007.98 3883.05,4043.05 U14.12@3955.76,4043.05
PG_1V5_GTY: R83.1 U13.12 | length 153.4
  Top Layer w12: R83.1@3877.98,5032.32 3877.98,5060.16 3920.87,5103.05 U13.12@3985.76,5103.05
PG_2V5_DDR: U21.16 | length 52.2
  Top Layer w10: U21.16@4326.14,2007.91 4326.14,1987.46 v9(4348.56,1965.05)
PG_3V3_VCCO: U22.16 | length 58.2
  Top Layer w10: U22.16@5871.7,6212.92 5901.46,6212.92 5920.55,6193.83 v9(5920.55,6192.35)
PGOOD_6003_0V8: pad.22 R54.1 | length 1064.2
  Top Layer w10: v1@1682.01,3660 v1(1682.01,3665) 1682.41,3665.4 1682.41,3714.77 pad.22@1682.81,3715.16
  Top Layer w15: R54.1@1460,2831.07 v5(1460,2890)
  Signal Layer 5 w15: v5(1460,2890) 1360,2990 1360,3342.99 v1(1682.01,3665)
PS_0V8: R11.2 U1.2 | length 222.9
  Top Layer w15: R11.2@2100,3888.54 2100,3848.79 2108.79,3840 2190,3840 2221.1,3808.9 U1.2@2266.65,3808.9
REF_0V92: R108.2 U15.18 | length 223.6
  Top Layer w15: R108.2@4211.6,2847.34 4212.58,2847.34 4223.78,2858.54 4223.78,2883.78 4236.89,2896.89 4249.92,2896.89 4263.03,2910 4263.03,2993.31 4252.1,3004.23 4221.36,3004.23 U15.18@4220,3005.59
REF_1V5: R93.2 U14.18 | length 227.6
  Top Layer w15: R93.2@4180.17,3902.59 4180,3902.76 4180,3930 4230,3980 4230,4059.85 4221.21,4068.64 U14.18@4184.11,4068.64
REF_1V5_GTY: R91.2 U13.18 | length 242.5
  Top Layer w15: R91.2@4210.17,4962.59 4212.76,4960 4240,4960 4257.13,4977.13 4257.13,5116.36 4246.21,5127.28 4215.46,5127.28 U13.18@4214.11,5128.64
REFCAP_0V8: C23.1 U1.20 | length 122.2
  Top Layer w15: U1.20@2495,3732.13 2572.13,3732.13 2580,3740 2600.41,3740 C23.1@2610,3749.59
REFCAP_SEQ1: C86.1 U3.5 | length 127.2
  Top Layer w15: C86.1@1690,2570 1707.5,2587.5 1775.57,2587.5 1778.07,2590 U3.5@1808.88,2590
REFCAP_SEQ2: C91.1 U5.5 | length 123.3
  Top Layer w15: C91.1@1691.99,1875.55 1707.69,1891.24 U5.5@1808.76,1891.24
REG_SEQ1: R58.2 U3.10 | length 175.9
  Top Layer w12: U3.10@1808.88,2465 1811.44,2462.44 1850.19,2462.44 1860.25,2452.38 1860.25,2413.9 1840,2393.66 R58.2@1840,2341.5
REG_SEQ2: R73.2 U5.10 | length 154.9
  Top Layer w15: R73.2@1731.99,1667.05 1731.99,1730.35 1767.89,1766.24 U5.10@1808.76,1766.24
RSC_0V8: R13.2 U1.21 | length 240
  Top Layer w15: U1.21@2495,3757.72 2542.72,3757.72 2580,3795 2670,3795 2680,3785 R13.2@2680,3749.59
RT_0V8: R12.2 U1.1 | length 131.4
  Top Layer w15: R12.2@2170,3888.54 2233.72,3888.54 2266.65,3855.61 U1.1@2266.65,3834.49
RT_1V2: R123.2 U18.9 | length 325.3
  Top Layer w10: R123.2@5600.99,2854.7 5614.69,2868.4 5625.76,2868.4 5660,2902.64 5660,2970 5628.52,3001.48 5628.52,3101.31 5634.38,3107.17 U18.9@5660.87,3107.17
RT_1V2_MEM: R133.2 U20.9 | length 324.2
  Top Layer w10: R133.2@5572.36,3903.15 5586.06,3916.85 5597.12,3916.85 5630,3949.73 5630,4040 5599.89,4070.11 5599.89,4149.76 5605.75,4155.62 U20.9@5632.23,4155.62
RT_1V2_VCCO: R124.2 U19.9 | length 320.6
  Top Layer w10: R124.2@5576.7,4939.6 5590.4,4953.3 5601.47,4953.3 5630,4981.83 5630,5060 5604.24,5085.76 5604.24,5186.22 5610.09,5192.07 U19.9@5636.58,5192.07
RT_2V5_DDR: R134.2 U21.9 | length 326.1
  Top Layer w10: R134.2@4122.56,1794.81 4136.26,1808.51 4147.32,1808.51 4182.44,1843.62 4182.44,1927.56 4150.09,1959.91 4150.09,2041.43 4155.95,2047.28 U21.9@4182.44,2047.28
RT_3V3_VCCO: R140.2 U22.9 | length 348.4
  Top Layer w10: R140.2@5685.43,5972.13 5691.38,5978.08 5691.38,6006.3 5737.74,6052.67 5737.74,6076.59 5737.96,6076.8 5737.96,6085.91 5695.65,6128.22 5695.65,6246.43 5701.51,6252.29 U22.9@5728,6252.29
SP_0V8: R14.2 U1.3 | length 283.2
  Top Layer w15: R14.2@2030,3888.54 2030,3887.56 2067.89,3849.67 2067.89,3845.63 2094.52,3819 2180,3819 2215.69,3783.31 U1.3@2266.65,3783.31
SS_SET_0V92: C135.1 R107.2 U15.19 | length 376.1
  Top Layer w15: U15.19@4220,3031.18 4264.13,3031.18 4303.55,2991.76 R107.2@4303.55,2874.22 4303.55,2873.23 4292.35,2862.03 4274.95,2862.03 4266.16,2853.25 4266.16,2826.16 4240,2800 4240,2775.59 4242.48,2773.11 C135.1@4228.33,2758.96
SS_SET_1V5: C113.1 R92.2 U14.19 | length 361.4
  Top Layer w15: U14.19@4184.11,4094.23 4235.77,4094.23 4267.74,4062.26 R92.2@4267.74,3929.47 4258.27,3920 4240,3920 4220,3900 4220,3870 4210,3860 4200.33,3860 4191.54,3851.21 C113.1@4191.54,3845.7
SS_SET_1V5_GTY: C110.1 R90.2 U13.19 | length 369.6
  Top Layer w12: C110.1@4226.9,4874.21 4242.56,4889.86 4242.56,4926.65 4274.07,4958.16 4282.97,4958.16 4290,4965.19 4290,4981.73 R90.2@4297.74,4989.47
  Top Layer w15: U13.19@4214.11,5154.23 4215.46,5152.87 4250.32,5152.87 4297.74,5105.46 R90.2@4297.74,4989.47
STAB_0V92: C137.1 U15.20 | length 136.8
  Top Layer w15: U15.20@4220,3056.77 4282.02,3056.77 4300,3038.79 C137.1@4349.39,3038.79
STAB_1V5: C116.1 U14.20 | length 144.5
  Top Layer w15: U14.20@4184.11,4119.82 4250.18,4119.82 4260,4110 4302,4110 C116.1@4317.96,4094.04
STAB_1V5_GTY: C112.1 U13.20 | length 144.5
  Top Layer w15: U13.20@4214.11,5179.82 4280.18,5179.82 4300,5160 4342,5160 C112.1@4347.96,5154.04
SW_0V8: C29.2 C30.2 C31.2 D2.1 D3.1 J1.1 L1.1 pad.1 pad.2 pad.3 pad.4 pad.5 pad.6 pad.7 pad.9 pad.10 pad.11 pad.12 pad.13 pad.44 pad.45 pad.46 pad.47 pad.57 Q1.4 Q1.5 Q2.3 Q3.3 Q4.3 R22.1 R31.1 TP8.1 | length 1482.1
  Top Layer w10: pad.1@1269.42,3715.16 pad.2@1289.11,3715.16 ; pad.2@1289.11,3715.08 1289.2,3715.16 pad.3@1308.79,3715.16 ; pad.3@1308.79,3715.08 1308.88,3715.16 pad.4@1328.48,3715.16 pad.57@1328.48,3798.83 ; pad.4@1328.48,3715.08 1328.57,3715.16 pad.6@1367.85,3715.16 pad.7@1387.53,3715.16
  Top Layer w35: TP8.1@570,5520 579.95,5510.05 772.46,5510.05 792.41,5530 J1.1@810,5530 815.05,5524.95 912.5,5524.95 968.94,5468.5 R31.1@1050,5468.5 1050,5467.52 1051.2,5466.32 L1.1@1362.78,5466.32 ; R22.1@1200,3940 1274.9,3940 pad.57@1275.33,3939.57 ; Q2.3@1435.49,4180.91 1460,4150 ; C30.2@1477.29,3602.75 1478.27,3602.75 1479.47,3601.55 1479.47,3570.77 1492.5,3557.74 1492.5,3517.5 C31.2@1500,3510 1492.5,3502.5 1492.5,3418.24 1500.74,3410 D2.1@1544.71,3410 ; C29.2@1478.29,4138.11 1478.29,4124 1485.79,4116.5 C29.2@1485.79,4110 ; L1.1@1362.78,5466.32 L1.1@1380,5449.1 L1.1@1362.78,5466.32
SW_1V2: C145.2 L2.1 TP71.1 U18.1 U18.2 U18.3 U18.4 U18.5 | length 308.5
  Top Layer w25: TP71.1@5250.23,3239.51 5368.85,3239.51 ; L2.1@5393.99,3266.01 L2.1@5462.49,3266.01 5454.69,3258.21 C145.2@5454.69,3147.87
SW_1V2_MEM: C166.2 L4.1 TP84.1 U20.1 U20.2 U20.3 U20.4 U20.5 | length 312.8
  Top Layer w25: TP84.1@5220,4290 5222.04,4287.96 5240.37,4287.96 5381.41,4287.96 ; C166.2@5418.19,4204.19 C166.2@5426.06,4196.32 L4.1@5426.06,4295.39 ; L4.1@5418.19,4301.93 5428.69,4312.43 L4.1@5454.25,4312.43
SW_1V2_VCCO: C146.2 L3.1 TP70.1 U19.1 U19.2 U19.3 U19.4 U19.5 | length 305.3
  Top Layer w25: TP70.1@5240,5340 5251.86,5328.14 L3.1@5389.79,5328.14 ; C146.2@5422.54,5240.64 C146.2@5430.4,5232.78 L3.1@5430.4,5331.84 ; L3.1@5422.54,5338.38 5433.04,5348.88 L3.1@5458.59,5348.88
SW_2V5_DDR: C167.2 L5.1 TP85.1 U21.1 U21.2 U21.3 U21.4 U21.5 | length 326.1
  Top Layer w25: TP85.1@3760,2180 3896.2,2180 ; L5.1@3915.56,2206.13 L5.1@3984.06,2206.13 3976.26,2198.32 C167.2@3976.26,2087.99
SW_3V3_VCCO: C187.2 L6.1 TP96.1 U22.1 U22.2 U22.3 U22.4 U22.5 | length 332.8
  Top Layer w25: TP96.1@5246.23,6384.63 5376.69,6384.63 ; C187.2@5438.41,6237.67 5438.41,6372.66 5460.95,6395.19 L6.1@5496.45,6395.19
SYNC_0V8: TP4.1 U1.6 | length 463
  Top Layer w12: TP4.1@2260,3360 2260,3485 2367.28,3592.28 2367.28,3657.67 2318.42,3706.54 U1.6@2266.65,3706.54
SYS_READY: R116.2 U5.13 | length 1550.4
  Top Layer w15: R116.2@910,1500 v7(1360,1500) ; U5.13@2213.87,1766.24 2214.94,1765.18 2255.81,1765.18 2269.04,1751.95 2269.04,1720.96 v1(2270,1720)
  Signal Layer 2 w15: v7(1360,1500) 2060,1500 2164.52,1604.52 2164.52,1614.52 v1(2270,1720)
SYS_RESTART: C85.1 R59.1 R60.2 SW1.1 SW2.1 SW2.3 TP29.1 U3.8 | length 3493.3
  Top Layer w10: U3.8@1808.88,2515 1805.32,2511.44 1767.98,2511.44 1748.5,2491.96 1748.5,2426.61 1700,2378.11 R60.2@1700,2339.6 1700,2315.86 1705.86,2310 1904.14,2310 1910,2304.14 1910,2300 R59.1@1910,2278.5
  Top Layer w15: SW2.1@233.5,838.58 SW2.3@546.5,838.58 546.5,1111.59 468.09,1190 SW1.1@420,1190 ; TP29.1@1370,1920 1380,1920 1466.89,2006.89 1466.89,2256.89 1560,2350 C85.1@1620,2350
  Top Layer w25: C85.1@1620,2350 1625.2,2344.8 1694.8,2344.8 R60.2@1700,2339.6
  Signal Layer 2 w15: v7(546.5,900) 596.5,950 975.09,950 1238.11,1213.02 1238.11,1778.11 1370,1910 TP29.1@1370,1920
SYS_SEQ_DOWN: R74.1 R75.2 SW3.1 SW3.3 U5.16 | length 2047.4
  Top Layer w12: R74.1@2151.99,1667.05 2151.99,1732.93 2138,1746.92 2138,1809.24 2170,1841.24 U5.16@2213.87,1841.24
  Top Layer w25: SW3.1@883.5,838.58 SW3.3@1196.5,838.58 1196.5,887.03 1211.14,901.67 1381.67,901.67 v7(2020,1540) ; R74.1@2151.99,1667.05 2190,1667.05 R75.2@2221.99,1667.05 ; v7(2185,1710) 2185.96,1709.04 2185.81,1668.79
  Signal Layer 2 w25: v7(2020,1540) v7(2185,1710) 2184.04,1709.04 v7@2184.04,1704.04
VCC_1V2: C160.1 U18.7 | length 186.3
  Top Layer w10: C160.1@5546.5,3045.9 5550.64,3041.77 5566.5,3057.64 5566.5,3096.03 5582.62,3112.14 5582.62,3119.56 5609.61,3146.54 U18.7@5660.87,3146.54
VCC_1V2_MEM: C181.1 U20.7 | length 186.3
  Top Layer w10: C181.1@5517.87,4094.35 5522,4090.22 5537.87,4106.09 5537.87,4144.48 5553.99,4160.59 5553.99,4168.01 5580.97,4194.99 U20.7@5632.23,4194.99
VCC_1V2_VCCO: C161.1 U19.7 | length 186.3
  Top Layer w10: C161.1@5522.22,5130.81 5526.35,5126.67 5542.22,5142.54 5542.22,5180.93 5558.33,5197.05 5558.33,5204.46 5585.32,5231.44 U19.7@5636.58,5231.44
VCC_2V5_DDR: C182.1 U21.7 | length 186.3
  Top Layer w10: C182.1@4068.07,1986.02 4072.21,1981.88 4088.07,1997.75 4088.07,2036.14 4104.19,2052.26 4104.19,2059.67 4131.18,2086.65 U21.7@4182.44,2086.65
VCC_3V3_VCCO: C194.1 U22.7 U22.17 | length 629.6
  Top Layer w10: v1(5570,6230) 5570,6237.81 5575.86,6243.67 C194.1@5622.24,6243.67 5622.24,6282.68 5628.1,6288.53 5674.66,6288.53 5677.79,6291.66 U22.7@5728,6291.66 ; U22.17@5871.7,6232.61 5911.28,6232.61 5914.62,6229.26 v12(5917.33,6229.26)
  Signal Layer 2 w10: v1(5570,6230) 5590.21,6209.79 5908.3,6209.79 5915.42,6216.91 5915.42,6229.08 v12@5917.33,6231
VLDO_0V8: C19.1 R5.1 U1.17 | length 797.3
  Top Layer w15: v5(2028.33,3824.03) 2029.17,3823.2 2029.17,3765.93 R5.1@2030,3765.1 ; v5(2420,3655.36) U1.17@2495,3655.36 2549.65,3655.36 2586,3619 2609.05,3619 2620,3608.05 C19.1@2620,3575.59 C19.1@2605,3590.59
  Signal Layer 2 w15: v5(2028.33,3824.03) 2256.25,3824.03 2256.25,3819.11 v5(2420,3655.36)
VLDO_SEQ1: C83.1 R53.2 U3.15 | length 1051.5
  Top Layer w15: v11(1480,2430) R53.2@1538.5,2430 ; U3.15@2214,2515 2215.06,2513.94 2269.26,2513.94 2275.94,2507.26 2322.74,2507.26 C83.1@2340,2490
  Signal Layer 2 w15: v11(1480,2430) 1748.95,2430 1778.69,2400.26 2173,2400.26 v7(2280,2507.26)
VLDO_SEQ2: C90.2 R68.2 U5.4 U5.15 | length 1252.7
  Top Layer w12: R68.2@1540.5,1745.55 1530,1756.05 1530,1921.5 1548.5,1940 v11(1670,1940) 1693.76,1916.24 U5.4@1808.76,1916.24 ; C90.2@2315.75,1816.24 C90.2@2331.99,1800
  Top Layer w15: U5.15@2213.87,1816.24 v11(2270,1816.24) C90.2@2315.75,1816.24
  Signal Layer 2 w12: v11(1670,1940) 1845.25,1940 1940.85,1844.4 2241.84,1844.4 v11(2270,1816.24)
VSENSE_0V8: R2.1 R4.2 TP3.1 U1.23 | length 430.6
  Top Layer w15: U1.23@2496.1,3810 U1.23@2495,3808.9 2533.9,3808.9 2580.61,3855.61 2607.07,3855.61 R4.2@2610,3858.54 ; 2645,3858.54 2645,4036.4 2646.22,4037.62 2646.22,4076.22 TP3.1@2650,4080
  Top Layer w25: R4.2@2610,3858.54 2645,3858.54 R2.1@2680,3858.54
pads on no net: FID1.1 FID2.1 FID3.1 H1.1 H2.1 H3.1 H4.1 H5.0 H6.0 H7.0 H8.0 Q1.2 Q2.2 Q3.2 Q4.2 Q5.9@2781.22,5503.7 Q5.9@2781.22,5560 Q5.9@2781.22,5616.3 Q5.9@2830.04,5560 Q5.9@2833.98,5503.7 Q5.9@2833.98,5560 Q5.9@2833.98,5616.3 Q5.9@2886.73,5503.7 Q5.9@2886.73,5560 Q5.9@2886.73,5616.3 U3.13 U4.6 U5.19 U6.6 U7.6 U8.6 U9.4 U9.6 U9.8 U9.10 U9.12 U10.6 U11.6 U12.6 U18.10 U19.10 U20.10 U21.10 U22.10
